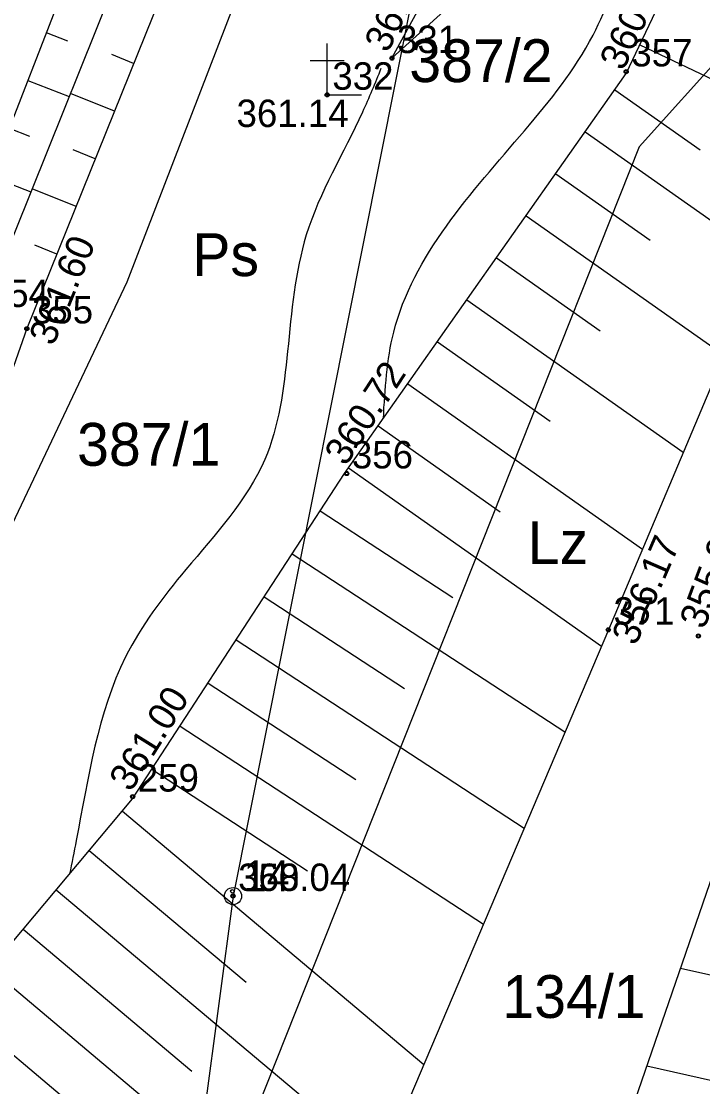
# Model space of a CAD drawing. Extents: x 4635329 to 4651863, y 5356628 to 5367582.
# Drawn here: x 4651745.45 to 4651765.35, y 5357153.92 to 5357185.01 of the extents above; entities that cross this region are included whole.
import ezdxf

# ---------------------------------------------------------------- set-up
doc = ezdxf.new("R2010")
doc.units = 0
for name, color, linetype in [('Level 12', 7, 'Continuous'), ('Level 4', 7, 'Continuous'), ('Level 44', 7, 'Continuous'), ('Level 45', 7, 'Continuous'), ('Level 46', 7, 'Continuous'), ('Level 48', 7, 'Continuous'), ('Level 5', 7, 'Continuous'), ('Level 50', 7, 'Continuous'), ('Level 54', 7, 'Continuous'), ('Level 62', 7, 'Continuous'), ('Level 63', 7, 'Continuous'), ('Level 7', 7, 'Continuous')]:
    doc.layers.add(name, color=color, linetype=linetype)

msp = doc.modelspace()

# ---------------------------------------------------------------- linework, layer by layer
at = {"layer": 'Level 4'}
for p, q in [((4651748.54, 5357177.401), (4651762.4, 5357213.326)), ((4651760.91, 5357206.04), (4651751.63, 5357159.48)), ((4651783.305, 5357203.355), (4651763.487, 5357181.344)), ((4651763.487, 5357181.344), (4651750.024, 5357147.467)), ((4651739.93, 5357159.265), (4651748.54, 5357177.401)), ((4651751.63, 5357159.48), (4651750.024, 5357147.467))]:
    msp.add_line(p, q, dxfattribs=at)
at = {"layer": 'Level 44'}
for centre in [(4651756.27, 5357183.93), (4651763.11, 5357183.54), (4651754.38, 5357182.86), (4651745.61, 5357176.04), (4651754.95, 5357171.81), (4651762.59, 5357167.25), (4651765.22, 5357167.07), (4651748.7, 5357162.38), (4651751.63, 5357159.48)]:
    msp.add_circle(centre, 0.04, dxfattribs=at)
at = {"layer": 'Level 46'}
for points in [[(4651756.02, 5357173.414), (4651756.322, 5357175.932), (4651760.142, 5357181.815), (4651762.143, 5357184.605), (4651762.871, 5357187.213), (4651762.689, 5357188.972), (4651762.659, 5357189.841)], [(4651755.951, 5357183.628), (4651755.408, 5357182.352), (4651753.771, 5357178.773), (4651753.225, 5357175.377), (4651752.558, 5357172.223), (4651750.254, 5357169.008), (4651748.495, 5357166.461), (4651747.051, 5357161.099), (4651746.856, 5357160.125)]]:
    msp.add_spline(points, degree=3, dxfattribs=at)
at = {"layer": 'Level 48'}
for p, q in [((4651746.179, 5357184.68), (4651746.793, 5357184.441)), ((4651763.508, 5357184.317), (4651768.744, 5357181.829)), ((4651748.729, 5357183.778), (4651748.087, 5357184.037)), ((4651745.635, 5357183.282), (4651746.849, 5357182.81)), ((4651762.78, 5357183.011), (4651765.271, 5357181.257)), ((4651748.168, 5357182.387), (4651746.886, 5357182.903)), ((4651745.091, 5357181.884), (4651745.69, 5357181.651)), ((4651761.916, 5357181.785), (4651767.165, 5357178.088)), ((4651747.607, 5357180.996), (4651746.967, 5357181.254)), ((4651744.548, 5357180.486), (4651745.73, 5357180.026)), ((4651761.052, 5357180.559), (4651763.81, 5357178.616)), ((4651747.047, 5357179.604), (4651745.767, 5357180.12)), ((4651760.189, 5357179.333), (4651765.971, 5357175.26)), ((4651746.486, 5357178.213), (4651745.847, 5357178.471)), ((4651759.325, 5357178.106), (4651762.349, 5357175.976)), ((4651758.461, 5357176.88), (4651764.777, 5357172.431)), ((4651757.597, 5357175.654), (4651760.889, 5357173.335)), ((4651756.733, 5357174.427), (4651763.583, 5357169.603)), ((4651755.87, 5357173.201), (4651759.428, 5357170.695)), ((4651755.006, 5357171.975), (4651762.388, 5357166.775)), ((4651754.18, 5357170.722), (4651758.05, 5357168.198)), ((4651753.361, 5357169.466), (4651761.324, 5357164.272)), ((4651752.542, 5357168.209), (4651756.635, 5357165.539)), ((4651751.722, 5357166.953), (4651760.133, 5357161.467)), ((4651750.903, 5357165.697), (4651755.22, 5357162.881)), ((4651750.083, 5357164.44), (4651758.941, 5357158.663)), ((4651749.264, 5357163.184), (4651753.804, 5357160.222)), ((4651748.399, 5357161.961), (4651757.2, 5357154.568)), ((4651747.434, 5357160.813), (4651752.01, 5357156.969)), ((4651746.469, 5357159.664), (4651755.973, 5357151.681)), ((4651745.504, 5357158.516), (4651750.432, 5357154.376)), ((4651744.54, 5357157.367), (4651754.746, 5357148.794)), ((4651773.467, 5357155.39), (4651764.696, 5357157.367)), ((4651743.575, 5357156.219), (4651748.854, 5357151.784)), ((4651772.807, 5357152.463), (4651763.714, 5357154.513))]:
    msp.add_line(p, q, dxfattribs=at)
for points in [[(4651757.59, 5357214.04), (4651748.24, 5357189.98), (4651743.2, 5357177.02), (4651738.89, 5357166.25), (4651736.04, 5357158.01)], [(4651737.04, 5357157.53), (4651740.4, 5357165.7), (4651744.32, 5357176.52), (4651749.53, 5357189.48), (4651758.92, 5357213.52)], [(4651760.39, 5357213.04), (4651750.91, 5357189.19), (4651745.61, 5357176.04), (4651741.85, 5357165.37), (4651738.55, 5357157.51)], [(4651756.27, 5357183.93), (4651769.94, 5357208.98)], [(4651771.4, 5357207.58), (4651762.54, 5357189.6), (4651756.27, 5357183.93)], [(4651742.61, 5357155.07), (4651748.7, 5357162.32), (4651754.89, 5357171.81), (4651763.11, 5357183.48), (4651765.69, 5357188.91), (4651773.53, 5357204.88)]]:
    msp.add_lwpolyline(points, dxfattribs=at)
at = {"layer": 'Level 50'}
for p, q in [((4651772.754, 5357191.33), (4651762.59, 5357167.25)), ((4651762.59, 5357167.25), (4651753.78, 5357146.52)), ((4651760.04, 5357143.84), (4651767.53, 5357165.6))]:
    msp.add_line(p, q, dxfattribs=at)
at = {"layer": 'Level 54'}
for p, q in [((4651754.38, 5357182.86), (4651754.38, 5357184.36)), ((4651753.88, 5357183.86), (4651754.88, 5357183.86)), ((4651754.38, 5357182.86), (4651755.38, 5357182.86))]:
    msp.add_line(p, q, dxfattribs=at)
at = {"layer": 'Level 62'}
msp.add_circle((4651751.61, 5357159.62), 0.05, dxfattribs=at)
at = {"layer": 'Level 63'}
for centre in [(4651756.27, 5357183.93), (4651763.11, 5357183.54), (4651754.38, 5357182.86), (4651745.61, 5357176.04), (4651754.95, 5357171.81), (4651762.59, 5357167.25), (4651765.22, 5357167.07), (4651748.7, 5357162.38), (4651751.63, 5357159.48)]:
    msp.add_circle(centre, 0.06, dxfattribs=at)
at = {"layer": 'Level 7'}
msp.add_circle((4651751.63, 5357159.48), 0.25, dxfattribs=at)

# ---------------------------------------------------------------- texts
at = {"layer": 'Level 12'}
for s, p in [('Ps', (4651750.439, 5357177.572)), ('Lz', (4651760.237, 5357169.169))]:
    msp.add_text(s, height=1.25, dxfattribs=at).set_placement(p)
at = {"layer": 'Level 45'}
for s, rotation, p in [('361.01', 63.9684, (4651756.15, 5357184.057)), ('360.27', 65.0784, (4651763.027, 5357183.534)), ('361.60', 67.6785, (4651746.385, 5357175.505)), ('360.72', 56.8433, (4651754.921, 5357171.997)), ('355.96', 69.4974, (4651765.393, 5357167.237)), ('356.17', 66.5308, (4651763.393, 5357166.759)), ('361.00', 58.0228, (4651748.645, 5357162.489))]:
    msp.add_text(s, height=0.8, rotation=rotation, dxfattribs=at).set_placement(p)
for s, p in [('361.14', (4651751.733, 5357181.922)), ('360.04', (4651751.78, 5357159.63))]:
    msp.add_text(s, height=0.8, dxfattribs=at).set_placement(p)
at = {"layer": 'Level 5'}
for s, p in [('387/2', (4651756.777, 5357183.232)), ('387/1', (4651747.077, 5357172.037)), ('134/1', (4651759.495, 5357155.925))]:
    msp.add_text(s, height=1.25, dxfattribs=at).set_placement(p)
at = {"layer": 'Level 62'}
msp.add_text(' 14', height=0.9, dxfattribs=at).set_placement((4651751.61, 5357159.62))
at = {"layer": 'Level 63'}
for s, p in [('331', (4651756.42, 5357184.08)), ('357', (4651763.26, 5357183.69)), ('332', (4651754.53, 5357183.01)), ('354', (4651744.47, 5357176.67)), ('355', (4651745.76, 5357176.19)), ('356', (4651755.1, 5357171.96)), ('371', (4651762.74, 5357167.4)), ('259', (4651748.85, 5357162.53)), ('358', (4651751.78, 5357159.63))]:
    msp.add_text(s, height=0.8, dxfattribs=at).set_placement(p)

doc.saveas('drawing.dxf')
